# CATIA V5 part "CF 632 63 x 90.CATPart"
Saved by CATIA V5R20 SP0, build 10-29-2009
Part number: CF 632 63 x 90
Definition: NONE
Nomenclature: CF 632 63 x 90
Source: Unknown
Description: CF 632 63 x 90
Bounding box of the stored display mesh (mm): x -13 to 77, y -46 to 46, z -46 to 46
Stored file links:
  C:\Users\Utente\Desktop\IO LAVORO\3D X SITO CF\X SITO\CF 632\CF 632 63 x 90.CATPart
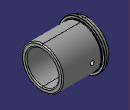
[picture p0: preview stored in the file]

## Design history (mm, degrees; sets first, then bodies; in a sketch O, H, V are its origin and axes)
Body1 "CF 632 63 x 90" (main body)
  Solid1: solid without history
